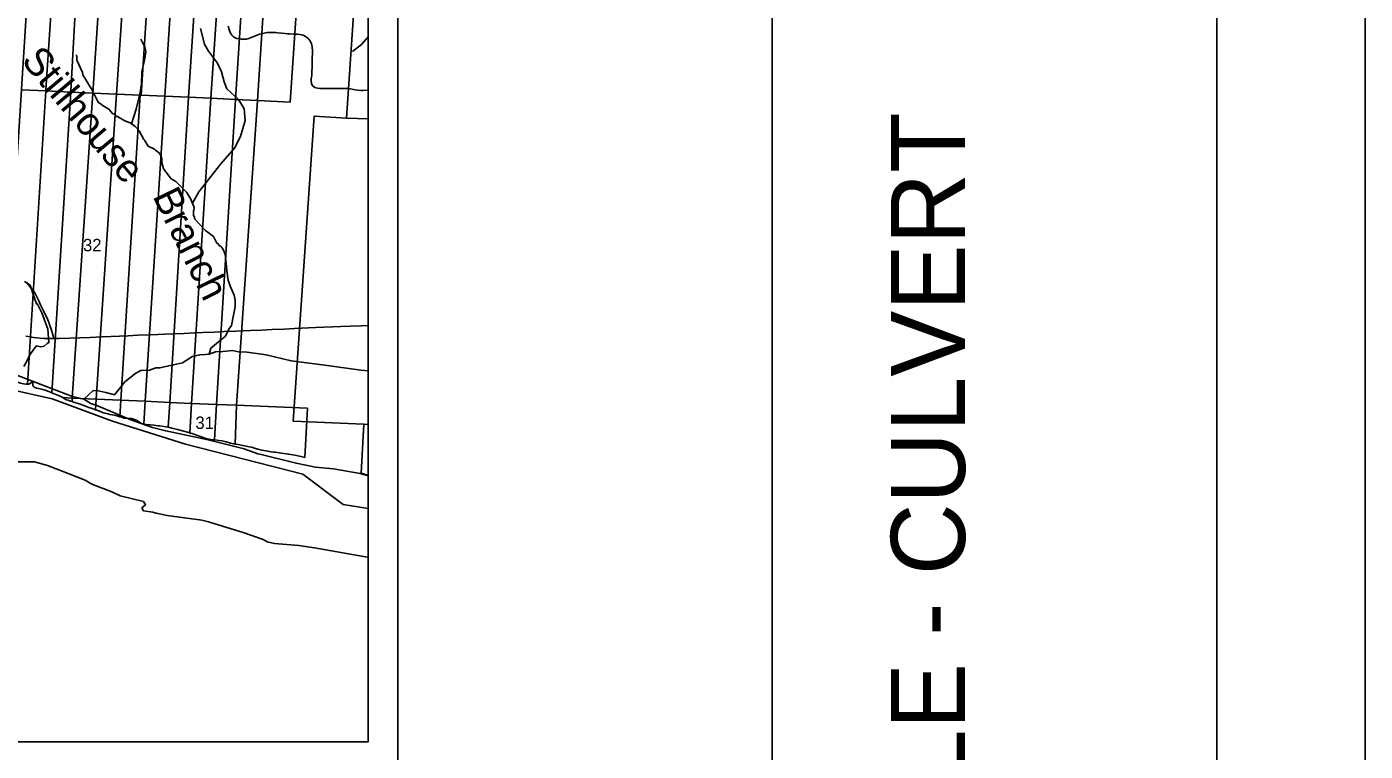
# Model space of a CAD drawing. Extents: x 0 to 34, y 0 to 22.
# Drawn here: x 29.485 to 34, y 14.068 to 16.511 of the extents above; entities that cross this region are included whole.
import ezdxf

# ---------------------------------------------------------------- set-up
doc = ezdxf.new("R2010")
doc.units = 0
for name, color, linetype in [('GM_X_County_Road', 7, 'Continuous'), ('GM_X_County_Text', 7, 'Continuous'), ('GM_X_Major_River', 7, 'Continuous'), ('GM_X_Minor_River', 7, 'Continuous'), ('GM_X_Minor_River_Text', 7, 'Continuous'), ('GM_X_Section', 7, 'Continuous'), ('GM_X_Section_Text', 7, 'Continuous'), ('GM_X_State_Route', 7, 'Continuous'), ('GM_X_State_Shield', 7, 'Continuous'), ('SH_Border', 7, 'Continuous'), ('SH_Cut_Line', 7, 'Continuous'), ('SH_Data', 7, 'Continuous')]:
    doc.layers.add(name, color=color, linetype=linetype)

msp = doc.modelspace()

# ---------------------------------------------------------------- linework, layer by layer
at = {"layer": 'GM_X_County_Road'}
for points in [[(30.6372, 16.2974), (30.6333, 16.2972), (30.6203, 16.2968), (30.6116, 16.297), (30.6013, 16.2977), (30.5932, 16.2988), (30.5776, 16.3017), (30.57, 16.3027), (30.5633, 16.3033), (30.5565, 16.3035), (30.5367, 16.3032), (30.517, 16.3033), (30.5073, 16.3034), (30.4868, 16.3034), (30.4743, 16.3037), (30.4656, 16.3046), (30.4612, 16.3056), (30.4571, 16.307), (30.4526, 16.3094), (30.4507, 16.311), (30.4486, 16.3134), (30.447, 16.3164), (30.4459, 16.3193), (30.4452, 16.3225), (30.4447, 16.3256), (30.4446, 16.3297), (30.445, 16.3344), (30.4456, 16.3421), (30.4463, 16.3475), (30.4468, 16.3534), (30.4473, 16.3615), (30.4475, 16.3744), (30.4479, 16.4028), (30.4486, 16.4244), (30.4485, 16.4336), (30.4483, 16.4391), (30.4477, 16.4448), (30.4468, 16.4496), (30.4455, 16.4544), (30.4439, 16.4585), (30.4402, 16.4648), (30.4368, 16.4693), (30.4331, 16.4731), (30.4291, 16.4761), (30.425, 16.4789), (30.4202, 16.4814), (30.4168, 16.4828), (30.4117, 16.4842), (30.4065, 16.4851), (30.3979, 16.4859), (30.3855, 16.4864), (30.3713, 16.487), (30.3657, 16.4874), (30.357, 16.4882), (30.3445, 16.4897), (30.3325, 16.4912), (30.3254, 16.4919), (30.316, 16.4924), (30.3076, 16.4925), (30.301, 16.4921), (30.296, 16.4916), (30.2908, 16.4907), (30.2812, 16.4886), (30.2718, 16.4861), (30.2593, 16.4819), (30.2366, 16.4733), (30.2305, 16.4711), (30.2265, 16.4699), (30.2213, 16.4694), (30.2165, 16.4693), (30.2089, 16.4696), (30.2006, 16.4705), (30.1943, 16.4719), (30.1891, 16.4736), (30.1858, 16.4754), (30.1816, 16.4782), (30.1772, 16.4826), (30.1749, 16.4859), (30.1731, 16.4888), (30.1716, 16.4921), (30.168, 16.5024), (30.1644, 16.5129)], [(29.577, 15.4595), (29.5745, 15.4677), (29.5682, 15.4881), (29.5622, 15.5071), (29.5586, 15.5172), (29.556, 15.5235), (29.5541, 15.5281), (29.5485, 15.5387), (29.5424, 15.5506), (29.5378, 15.5604), (29.5306, 15.5756), (29.5256, 15.5871), (29.5201, 15.5988), (29.5148, 15.6096), (29.5099, 15.6174), (29.505, 15.6241), (29.4945, 15.637), (29.4879, 15.6455), (29.4848, 15.6503)]]:
    msp.add_lwpolyline(points, dxfattribs=at)
at = {"layer": 'GM_X_County_Text'}
msp.add_lwpolyline([(29.4304, 15.2876), (29.5713, 15.2568), (29.7749, 15.1808), (30.0202, 15.1042), (30.4162, 15.0021), (30.5527, 14.9001), (30.6372, 14.8869), (30.6372, 20.3098), (29.547, 20.3639), (28.6062, 20.4055)], dxfattribs=at)
at = {"layer": 'GM_X_Major_River'}
for points in [[(30.6372, 14.9968), (30.61, 15.0048), (30.5198, 15.0203), (30.4595, 15.0266), (30.3939, 15.0391), (30.2756, 15.0693), (30.2642, 15.0712), (30.2184, 15.0885), (30.0974, 15.1184), (29.9541, 15.1481), (29.9094, 15.1602), (29.8358, 15.1855), (29.722, 15.2339), (29.7008, 15.2404), (29.6781, 15.2559), (29.6394, 15.2642), (29.5453, 15.3005), (29.4369, 15.3424)], [(29.419, 15.0438), (29.5115, 15.044), (29.5551, 15.0319), (29.5991, 15.0152), (29.6818, 14.982), (29.7042, 14.9691), (29.7717, 14.9434), (29.8001, 14.9298), (29.8786, 14.9098), (29.8858, 14.8992), (29.8733, 14.8889), (29.879, 14.8794), (29.9101, 14.8738), (29.9222, 14.8715), (29.9586, 14.8636), (30.0754, 14.8474), (30.0977, 14.8414), (30.2191, 14.8044), (30.2828, 14.7817), (30.296, 14.7745), (30.3207, 14.7692), (30.4029, 14.7625), (30.456, 14.7542), (30.6281, 14.7237), (30.6372, 14.7226)]]:
    msp.add_lwpolyline(points, dxfattribs=at)
at = {"layer": 'GM_X_Minor_River'}
for points in [[(30.0448, 15.9162), (30.0651, 15.9547), (30.1394, 16.0492), (30.186, 16.1016), (30.2065, 16.1416), (30.2218, 16.1957), (30.2188, 16.2346), (30.1997, 16.2663), (30.1603, 16.3017), (30.1509, 16.3252), (30.1425, 16.3596), (30.1282, 16.3882), (30.0981, 16.4294), (30.0852, 16.453), (30.0709, 16.5055)], [(29.8385, 16.1844), (29.8544, 16.2337), (29.8661, 16.285), (29.8717, 16.3193), (29.8737, 16.3591), (29.8834, 16.404), (29.8867, 16.4267), (29.8845, 16.4404), (29.8702, 16.4697)], [(30.6372, 16.4776), (30.6147, 16.4512), (30.5837, 16.4275)], [(29.9159, 16.0991), (29.8949, 16.1087), (29.8824, 16.1285), (29.8805, 16.1307), (29.8642, 16.1603), (29.8513, 16.1755), (29.8343, 16.1873), (29.8162, 16.1937), (29.7916, 16.2084), (29.7859, 16.2088), (29.7844, 16.2149), (29.7742, 16.2194), (29.7621, 16.2338), (29.7424, 16.2448), (29.7371, 16.2497), (29.7265, 16.2569), (29.7061, 16.2979), (29.6739, 16.3492), (29.6727, 16.3571), (29.6546, 16.3989), (29.6542, 16.4095), (29.6527, 16.4156), (29.6508, 16.4145)], [(29.6781, 15.2559), (29.7081, 15.2832), (29.7217, 15.2848), (29.7523, 15.278), (29.7807, 15.2705), (29.7992, 15.2922), (29.8162, 15.3139), (29.8528, 15.3436), (29.8698, 15.352), (29.8993, 15.3536), (29.9205, 15.3612), (29.9341, 15.3613), (29.99, 15.3739), (30.0101, 15.3785), (30.0384, 15.3961), (30.0437, 15.3991), (30.069, 15.4053), (30.0883, 15.4061), (30.1004, 15.4076), (30.106, 15.427), (30.1132, 15.4327), (30.1555, 15.4674), (30.1672, 15.491), (30.1759, 15.5036), (30.1827, 15.5386), (30.1883, 15.5663), (30.1879, 15.5891), (30.1845, 15.6066), (30.1724, 15.6339), (30.1644, 15.6567), (30.1606, 15.6879), (30.1602, 15.6913), (30.1541, 15.7445), (30.1477, 15.76), (30.1394, 15.7718), (30.1345, 15.7729), (30.1314, 15.7798), (30.1269, 15.782), (30.1148, 15.8037), (30.1061, 15.8109), (30.0879, 15.8245), (30.0701, 15.8435), (30.0512, 15.8639), (30.0523, 15.8674), (30.0474, 15.875), (30.0482, 15.8894), (30.0493, 15.8928), (30.0504, 15.9023), (30.0379, 15.9327), (30.0243, 15.954), (30.0073, 15.9703), (29.988, 15.99), (29.9728, 15.9983), (29.9653, 16.0078), (29.946, 16.0324), (29.9414, 16.0533), (29.9406, 16.0674), (29.9346, 16.0837), (29.9195, 16.0947), (29.9158, 16.0991)], [(29.4759, 15.3652), (29.4857, 15.3831), (29.4959, 15.4055), (29.5129, 15.4291), (29.5178, 15.4348), (29.5326, 15.4322), (29.5439, 15.4341), (29.5545, 15.4433), (29.5598, 15.4463), (29.556, 15.4915), (29.5363, 15.547), (29.5215, 15.5754), (29.5185, 15.5766), (29.5037, 15.6187), (29.5025, 15.6225), (29.4972, 15.6396), (29.4779, 15.6521)], [(30.1002, 15.4076), (30.1219, 15.4149), (30.1465, 15.4165), (30.179, 15.4192), (30.1994, 15.4155), (30.2282, 15.4144), (30.2924, 15.4046), (30.3767, 15.3843), (30.4909, 15.3701), (30.6119, 15.3537), (30.6372, 15.3506)]]:
    msp.add_lwpolyline(points, dxfattribs=at)
at = {"layer": 'GM_X_Section'}
for points in [[(29.6192, 17.3436), (29.5493, 16.2992), (29.5491, 16.295), (29.4674, 16.2986), (29.4676, 16.3015), (29.5335, 17.3481)], [(29.6912, 17.3401), (29.634, 16.2945), (29.6338, 16.2912), (29.5491, 16.295), (29.5493, 16.2992), (29.6192, 17.3436)], [(29.7781, 17.3351), (29.7082, 16.2879), (29.6338, 16.2912), (29.634, 16.2945), (29.6912, 17.3401)], [(29.8591, 17.3308), (29.7875, 16.2844), (29.7082, 16.2879), (29.7781, 17.3351)], [(29.9382, 17.3269), (29.8707, 16.2807), (29.8681, 16.2808), (29.7875, 16.2844), (29.8591, 17.3308)], [(30.0187, 17.3227), (29.9505, 16.2771), (29.8707, 16.2807), (29.9382, 17.3269)], [(30.0998, 17.3186), (30.0307, 16.2736), (29.9505, 16.2771), (30.0187, 17.3227)], [(30.177, 17.3146), (30.1058, 16.2702), (30.0307, 16.2736), (30.0998, 17.3186)], [(30.2563, 17.3105), (30.1897, 16.2665), (30.1058, 16.2702), (30.177, 17.3146)], [(30.331, 17.3066), (30.2635, 16.2632), (30.1897, 16.2665), (30.2563, 17.3105)], [(30.4442, 17.3015), (30.3733, 16.257), (30.2635, 16.2632), (30.331, 17.3066)], [(29.5491, 16.295), (29.4878, 15.3057), (29.4821, 15.3061), (29.4737, 15.3072), (29.4643, 15.3098), (29.4521, 15.3139), (29.4369, 15.3199), (29.4297, 15.3233), (29.4138, 15.3316), (29.4057, 15.3352), (29.4674, 16.2986)], [(29.6338, 16.2912), (29.5701, 15.277), (29.5648, 15.2791), (29.5469, 15.2854), (29.539, 15.2881), (29.531, 15.2899), (29.5253, 15.2918), (29.5177, 15.2929), (29.5128, 15.2948), (29.5086, 15.2971), (29.5067, 15.2989), (29.506, 15.3016), (29.5059, 15.3084), (29.5056, 15.3103), (29.5048, 15.3111), (29.5037, 15.3114), (29.5025, 15.3114), (29.4976, 15.3091), (29.4923, 15.3065), (29.4878, 15.3057), (29.5491, 16.295)], [(29.7082, 16.2879), (29.6388, 15.2593), (29.6066, 15.2607), (29.5955, 15.2667), (29.5837, 15.2715), (29.5701, 15.277), (29.6338, 16.2912)], [(29.7875, 16.2844), (29.7198, 15.2557), (29.6388, 15.2593), (29.7082, 16.2879)], [(29.8681, 16.2808), (29.8024, 15.252), (29.7198, 15.2557), (29.7875, 16.2844)], [(29.8707, 16.2807), (29.9505, 16.2771), (29.8847, 15.2483), (29.8024, 15.252), (29.8681, 16.2808)], [(30.0307, 16.2736), (29.9673, 15.2446), (29.8847, 15.2483), (29.9505, 16.2771)], [(30.1058, 16.2702), (30.0411, 15.2413), (29.9673, 15.2446), (30.0307, 16.2736)], [(30.1897, 16.2665), (30.1256, 15.2376), (30.0411, 15.2413), (30.1058, 16.2702)], [(30.2635, 16.2632), (30.1926, 15.2351), (30.1256, 15.2376), (30.1897, 16.2665)], [(29.6388, 15.2593), (29.6379, 15.2471), (29.6327, 15.2486), (29.6251, 15.2516), (29.6191, 15.2531), (29.6149, 15.2554), (29.6066, 15.2607)], [(29.7198, 15.2557), (29.7175, 15.2193), (29.7055, 15.2235), (29.6949, 15.2272), (29.6832, 15.2314), (29.6741, 15.2355), (29.6684, 15.2377), (29.6615, 15.24), (29.6547, 15.2422), (29.6429, 15.2456), (29.6379, 15.2471), (29.6388, 15.2593)], [(29.8024, 15.252), (29.7989, 15.1958), (29.7825, 15.201), (29.7731, 15.2029), (29.7659, 15.204), (29.7598, 15.2055), (29.7484, 15.2085), (29.7408, 15.2107), (29.7306, 15.2149), (29.7215, 15.2178), (29.7175, 15.2193), (29.7198, 15.2557)], [(29.8847, 15.2483), (29.8798, 15.1714), (29.8728, 15.1733), (29.8705, 15.1748), (29.8591, 15.182), (29.8546, 15.1846), (29.8462, 15.188), (29.8387, 15.1898), (29.8292, 15.1906), (29.8155, 15.1909), (29.8125, 15.1916), (29.808, 15.1931), (29.7989, 15.1958), (29.8024, 15.252)], [(29.9673, 15.2446), (29.9622, 15.1609), (29.9547, 15.1626), (29.9471, 15.1637), (29.9327, 15.1652), (29.9278, 15.1659), (29.9153, 15.1678), (29.9031, 15.1692), (29.888, 15.1699), (29.8798, 15.1714), (29.8847, 15.2483)], [(30.0411, 15.2413), (30.0348, 15.1412), (30.0321, 15.1428), (30.0275, 15.1443), (30.0104, 15.1488), (29.9941, 15.1529), (29.979, 15.1566), (29.9665, 15.16), (29.9622, 15.1609), (29.9673, 15.2446)], [(30.1256, 15.2376), (30.1182, 15.1183), (30.1117, 15.1188), (30.1003, 15.121), (30.0924, 15.1222), (30.0856, 15.1244), (30.0745, 15.1281), (30.0548, 15.1353), (30.0434, 15.1394), (30.0377, 15.1409), (30.0348, 15.1412), (30.0411, 15.2413)], [(30.1926, 15.2351), (30.1885, 15.1042), (30.1834, 15.1053), (30.1724, 15.1076), (30.1583, 15.1114), (30.1439, 15.1144), (30.1326, 15.1162), (30.1212, 15.1181), (30.1182, 15.1183), (30.1256, 15.2376)], [(30.1926, 15.2351), (30.4318, 15.2246), (30.4227, 15.0588), (30.4101, 15.0623), (30.3953, 15.0652), (30.3828, 15.0675), (30.3684, 15.0701), (30.3529, 15.0723), (30.3362, 15.0749), (30.3244, 15.0764), (30.3191, 15.0763), (30.3093, 15.0782), (30.293, 15.0808), (30.2786, 15.0834), (30.2641, 15.0868), (30.2539, 15.0901), (30.2429, 15.0931), (30.2349, 15.0946), (30.2304, 15.0953), (30.2258, 15.0969), (30.2137, 15.0987), (30.1985, 15.1021), (30.1885, 15.1042)]]:
    msp.add_lwpolyline(points, close=True, dxfattribs=at)
at = {"layer": 'GM_X_State_Route'}
msp.add_lwpolyline([(29.4825, 15.4681), (29.4963, 15.4658), (29.5085, 15.4639), (29.5196, 15.4624), (29.5301, 15.4612), (29.5437, 15.4603), (29.5591, 15.4597), (29.577, 15.4595), (29.5951, 15.4599), (29.6305, 15.461), (29.6982, 15.4639), (29.7398, 15.4656), (29.8273, 15.4694), (29.8602, 15.4709), (29.8993, 15.4726), (29.9272, 15.4737), (29.9514, 15.4746), (29.9788, 15.4758), (30.0161, 15.4774), (30.0515, 15.4791), (30.0792, 15.4802), (30.1185, 15.4818), (30.1508, 15.4832), (30.1903, 15.485), (30.2394, 15.487), (30.2771, 15.4887), (30.3132, 15.4903), (30.3523, 15.4919), (30.3889, 15.4935), (30.459, 15.4967), (30.5447, 15.5003), (30.5773, 15.5017), (30.613, 15.5032), (30.6372, 15.5042)], dxfattribs=at)
at = {"layer": 'GM_X_State_Shield'}
for points in [[(30.6372, 16.2007), (30.6372, 17.2479), (30.635, 17.248), (30.5641, 16.2036)], [(30.6372, 15.1704), (30.6372, 16.2007), (30.5641, 16.2036), (30.4543, 16.2098), (30.3833, 15.1817), (30.6226, 15.1712)], [(30.6372, 14.9989), (30.6372, 15.1704), (30.6226, 15.1712), (30.6135, 15.0054), (30.6206, 15.0032), (30.6316, 15.0002)]]:
    msp.add_lwpolyline(points, close=True, dxfattribs=at)
at = {"layer": 'SH_Border'}
msp.add_line((32, 0.5), (32, 21.5), dxfattribs=at)
msp.add_lwpolyline([(1.5, 21.5), (33.5, 21.5), (33.5, 0.5), (1.5, 0.5)], close=True, dxfattribs=at)
at = {"layer": 'SH_Cut_Line'}
msp.add_lwpolyline([(0, 0), (34, 0), (34, 22), (0, 22)], close=True, dxfattribs=at)
msp.add_lwpolyline([(29.4304, 15.2876), (29.5713, 15.2568), (29.7749, 15.1808), (30.0202, 15.1042), (30.4162, 15.0021), (30.5527, 14.9001), (30.6372, 14.8869), (30.6372, 20.9), (23.8372, 20.9)], dxfattribs=at)
at = {"layer": 'SH_Data'}
for points in [[(23.7372, 21), (30.7372, 21), (30.7372, 14), (23.7372, 14)], [(23.8372, 20.9), (30.6372, 20.9), (30.6372, 14.1), (23.8372, 14.1)]]:
    msp.add_lwpolyline(points, close=True, dxfattribs=at)

# ---------------------------------------------------------------- texts
at = {"layer": 'GM_X_Minor_River_Text'}
for s, rotation, p in [('Stillhouse', 310.1347, (29.4639, 16.3951)), ('Branch', 296.1346, (29.9083, 15.9404))]:
    msp.add_text(s, height=0.09469, rotation=rotation, dxfattribs=at).set_placement(p)
at = {"layer": 'GM_X_Section_Text'}
for s, p in [('32', (29.6751, 15.7542)), ('31', (30.0542, 15.1551))]:
    msp.add_text(s, height=0.04186, rotation=0, dxfattribs=at).set_placement(p)
at = {"layer": 'SH_Data'}
msp.add_text('GEOTECHNICAL PROFILE - CULVERT', height=0.25, rotation=90, dxfattribs=at).set_placement((32.65, 10.204))

doc.saveas('drawing.dxf')
